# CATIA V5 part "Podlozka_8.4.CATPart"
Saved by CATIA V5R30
Part number: Podlozka_8.4
Definition: DIN 6340-8.4_3
Nomenclature: DIN 6340-8.4_3
Source: Unknown
Description: PART--DESC
Bounding box of the stored display mesh (mm): x -138.5 to -120.5, y -27.5 to -9.5, z 83.7 to 86.2
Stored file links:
  E:\Bakalarka\Model\Forma_v7\Podlozka_8.4.CATPart
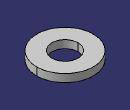
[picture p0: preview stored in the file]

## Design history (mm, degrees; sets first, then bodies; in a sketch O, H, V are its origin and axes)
Body1 "MANIFOLD_SOLID_BREP #3642" (main body)
  Solid1: solid without history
